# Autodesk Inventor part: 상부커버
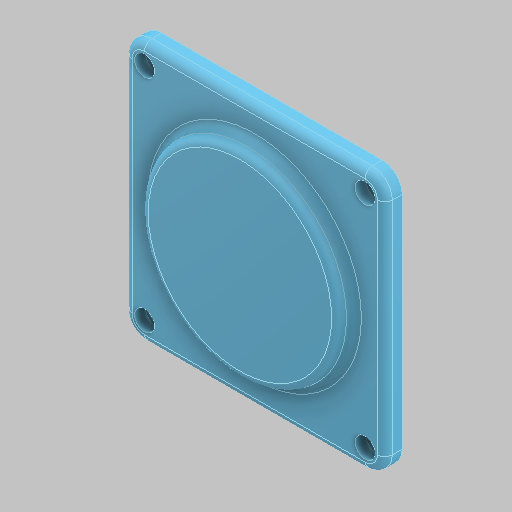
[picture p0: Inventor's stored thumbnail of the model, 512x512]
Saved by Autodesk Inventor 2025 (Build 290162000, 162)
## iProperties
Created: 2024-08
Part Number: 상부커버
Material: 알루미늄 6061
Document SubType Name: Modeling
Designer: 현기
Density: 2.71 g/cm^3
Appearance: 기본값
Author: jhkim
Sending System: Autodesk Inventor 2025
Preprocessor: ST-DEVELOPER v20
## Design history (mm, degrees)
feature "솔리드2"
node "솔리드1"
